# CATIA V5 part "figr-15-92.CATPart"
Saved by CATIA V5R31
Part number: Part1
Bounding box of the stored display mesh (mm): x -40 to 40, y -60 to 60, z 0 to 2
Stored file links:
  D:\PROJECTS\Project 2021\US EDITION\CATIA V5 6R 2021\Resources\Part Files\c15_catia_v5_6r2021_prt\figr-15-92.CATPart
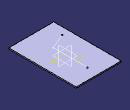
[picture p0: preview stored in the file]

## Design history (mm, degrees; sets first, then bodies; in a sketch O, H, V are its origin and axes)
SheetMetalParameters1: Thickness 2, BendRadius 4, KFactor 0.400515 {= log(min(100,max(20*SheetMetalParameters1.BendRadius,SheetMetalParameters1.Thickness)/SheetMetalParameters1.Thickness))/log(100)/2}, ReliefRadialLength 1, ReliefAxialLength 2, MinimumBendRadius 0
Body1 (main body)
  Sketch1 on xy-plane, origin (0, 0, 0), H (-1, 0, 0), V (0, -1, 0)
    line L1 (40, 60) -> (40, -60)
    line L2 (40, -60) -> (-40, -60)
    line L3 (-40, -60) -> (-40, 60)
    line L4 (-40, 60) -> (40, 60)
    length L4 = 80
    length L1 = 120
    vertical: L1 V, L3 V
    horizontal: L2 H, L4 H
    equidistance: L1 L3 O, L2 L4 O
  Wall1: Thickness 2, Profile Sketch1, OffsetValue 0
  Sketch2 on face of Wall1, origin (0, 0, 2), H (1, 0, 0), V (0, 1, 0)
    line L1 (0, 40.0798) -> (0, -21.0085)
    line L2 (0, -21.0085) -> (-27, -32)
    vertical: L1 V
